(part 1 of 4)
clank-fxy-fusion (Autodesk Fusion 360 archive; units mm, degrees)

design "AS_Clank-FXY" references "AS_FXY-Z-Idler", "Bus 30 Pinner Mount", "AS_FXY-Z-Drive", "AS_FXY-XY", "AS_FXY-Z-Limit", "Bus 3010 Terminal Mount", "AS_FXY-Loadcell-Bed", "PP_EXTR_Bracket-HBLFSN5-SET", "PP_FOOD_Banana-For-Scale"
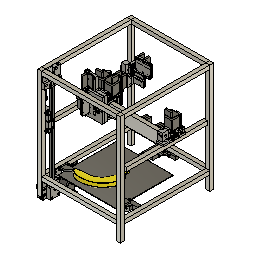
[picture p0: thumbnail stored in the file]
parameter "w_xcarr" = 107
parameter "w_ycarr" = 115.5
parameter "l_travel_x" = 256
parameter "l_travel_y" = 256
parameter "xbeam_w" = 20
parameter "xbeam_h" = 60
parameter "ybeam_w" = 20
parameter "ybeam_h" = 20
parameter "xcarr_rear_depth" = 65
parameter "yl_joint_sep" = 10
parameter "yr_joint_sep" = 11 (= "yl_joint_sep + 1 mm")
parameter "y_joints_inset" = 3
parameter "y_rear_depth" = 90
parameter "y_front_depth" = 27
parameter "l_bracket_inset" = 31
parameter "xcarr_front_depth" = 12.5
parameter "z_top_depth" = 126
parameter "z_lower_depth" = 30
parameter "l_travel_z" = 226
parameter "z_lower_offset" = 50
parameter "y_to_z_front" = 34
parameter "y_to_z_rear" = 35
sketch "Sketch1" plane through (0, 0, 0) normal (0, 0, 1) x axis (1, 0, 0)
  line L1 (369, 0) -> (0, 0)
  line L2 (369, 20) -> (369, 0)
  line L3 (0, 20) -> (369, 20)
  line L4 (0, 0) -> (0, 20)
  line L5 (-30, -51) -> (-10, -51)
  line L6 (-30, 391) -> (-30, -51)
  line L7 (-10, 391) -> (-30, 391)
  line L8 (-10, -51) -> (-10, 391)
  line L9 (400, -51) -> (380, -51)
  line L10 (400, 391) -> (400, -51)
  line L11 (380, 391) -> (400, 391)
  line L12 (380, -51) -> (380, 391)
  line L13 (-10, 393) -> (-30, 393)
  line L14 (-10, 413) -> (-10, 393)
  line L15 (-30, 413) -> (-10, 413)
  line L16 (-30, 393) -> (-30, 413)
  line L17 (-10, -53) -> (-30, -53)
  line L18 (-10, -73) -> (-10, -53)
  line L19 (-30, -73) -> (-10, -73)
  line L20 (-30, -53) -> (-30, -73)
  line L21 (380, 170) -> (-10, 170)
  line L22 (185, 20) -> (185, 170)
  line L23 (400, 393) -> (400, 413)
  line L24 (380, 393) -> (400, 393)
  line L25 (380, 413) -> (380, 393)
  line L26 (400, 413) -> (380, 413)
  line L27 (400, -53) -> (400, -73)
  line L28 (380, -53) -> (400, -53)
  line L29 (400, -73) -> (380, -73)
  line L30 (380, -73) -> (380, -53)
  line L31 (380, 393) -> (-10, 393)
  line L32 (-10, 413) -> (380, 413)
  line L33 (-30, 393) -> (-30, 391)
  line L34 (-10, 391) -> (-10, 393)
  line L35 (-30, -53) -> (-30, -51)
  line L36 (-10, -53) -> (-10, -51)
  line L37 (380, -53) -> (380, -51)
  line L38 (400, -53) -> (400, -51)
  line L39 (400, 393) -> (400, 391)
  line L40 (380, 391) -> (380, 393)
  line L41 (380, -73) -> (-10, -73)
  line L42 (380, -53) -> (-10, -53)
  point P1 (0, 0)
  point P2 (0, 0)
  point P6 (-10, -51)
  point P9 (-10, 391)
  point P8 (-30, 391)
  point P18 (-30, -53)
  point P19 (-10, -53)
  point P22 (-10, 170)
  point P23 (380, 170)
  point P24 (185, 170)
  point P25 (185, 170)
  point P26 (185, 20)
  point P27 (184.5, 20)
  point P14 (-30, 393)
  point P29 (400, 393)
  point P15 (-10, 393)
  point P30 (380, 393)
  point P16 (-10, 413)
  point P31 (380, 413)
  point P17 (-30, 413)
  point P28 (400, 413)
  point P33 (400, -53)
  point P34 (380, -53)
  point P20 (-10, -73)
  point P35 (380, -73)
  point P21 (-30, -73)
  point P32 (400, -73)
  point P36 (380, -51)
  point P7 (-30, -51)
  point P38 (400, -51)
  point P40 (400, 391)
  point P43 (380, 391)
  point P41 (400, 393)
  point P42 (380, 393)
  point P39 (400, -53)
  point P37 (380, -53)
  point P44 (0, 10)
  point P45 (-10, -53)
  point P46 (380, -53)
  point P5 (0, 20)
  point P3 (369, 0)
  point P13 (380, 391)
  horizontal L1
  vertical L2
  horizontal L3
  vertical L4
  coincident P1 P2
  horizontal L5
  vertical L6
  horizontal L7
  vertical L8
  horizontal L9
  vertical L10
  horizontal L11
  vertical L12
  equal L5 L9
  coincident P6 L9
  coincident P9 L11
  horizontal L13
  vertical L14
  horizontal L15
  vertical L16
  equal L15 L16
  coincident P8 L16
  coincident P9 L14
  horizontal L17
  vertical L18
  horizontal L19
  vertical L20
  coincident L6 P18
  coincident L8 P19
  midpoint L8 P22
  midpoint L12 P23
  midpoint L21 P24
  coincident P24 P25
  coincident L3 P26
  perpendicular L3 L22
  midpoint L3 P27
  symmetric P14 L22 P29
  symmetric P15 L22 P30
  symmetric P16 L22 P31
  symmetric P17 L22 P28
  symmetric P18 L22 P33
  symmetric P19 L22 P34
  symmetric P20 L22 P35
  symmetric P21 L22 P32
  symmetric P6 L22 P36
  symmetric P7 L22 P38
  symmetric P8 L22 P40
  symmetric P9 L22 P43
  symmetric P14 L22 P41
  symmetric P15 L22 P42
  symmetric P18 L22 P39
  symmetric P19 L22 P37
  midpoint L4 P44
  coincident P19 P45
  coincident P37 P46
  dimension "d15" distance P2 P5 = 20 (= "xbeam_w")
  dimension "d16" distance P2 P3 = 369 (= "l_travel_x + w_xcarr + 2 * y_joints_inset")
  dimension "d17" distance P1 L8 = 10 (= "yl_joint_sep")
  dimension "d18" distance P3 L12 = 11 (= "yr_joint_sep")
  dimension "d19" distance P6 P7 P13 = 20 (= "ybeam_w")
  dimension "d190" distance P7 P8 = 442 (= "l_travel_y + y_front_depth + y_rear_depth + y_to_z_front + y_to_z_rear")
  dimension "d193" distance P26 P27 = 0.5
  dimension "d198" distance P17 P21 = 486
  dimension "d199" distance P17 P28 = 430
  dimension "d272" distance L5 P44 = 61 (= "y_front_depth + y_to_z_front")
  dimension "d274" distance P8 P14 = 2
  dimension "d275" distance P18 P21 = 20
  dimension "d288" distance P7 L17 = 2
  dimension "d62" OffsetX = 0
  dimension "d63" OffsetY = 0
  dimension "d64" OffsetZ = 0
  dimension "d65" AngleZ = 0
  dimension "d74" OffsetX = 0
  dimension "d75" OffsetY = 0
  dimension "d76" OffsetZ = 0
  dimension "d77" AngleZ = 0
  dimension "d147" OffsetX = 0
  dimension "d148" OffsetY = 0
  dimension "d149" OffsetZ = 0
  dimension "d150" AngleZ = 0
  dimension "d155" OffsetX = 0
  dimension "d156" OffsetY = 0
  dimension "d157" OffsetZ = 0
  dimension "d158" AngleZ = 0
extrude "Extrude2" new body sketch "Sketch1" profile of L6 L8 L10 L12 L13 L17 L24 L28 L33 L34 L35 L36 L37 L38 L39 L40 along normal blind 20 (= "ybeam_h")
extrude "Extrude3" new body sketch "Sketch1" profile of L14 L18 L25 L30 L31 L32 L41 L42 along normal blind 20 (= "ybeam_h")
extrude "Extrude4" new body sketch "Sketch1" profile of L13 L14 L15 L16 L17 L18 L19 L20 L23 L24 L25 L26 L27 L28 L29 L30 along normal blind 496 (= "l_travel_z + z_lower_depth + z_top_depth + 114 mm") and against normal blind 75
extrude "Extrude5" sketch "Sketch1" profile of L6 L8 L10 L12 L13 L17 L24 L28 L33 L34 L35 L36 L37 L38 L39 L40 blind -20
extrude "Extrude6" sketch "Sketch1" profile of L14 L18 L25 L30 L31 L32 L41 L42 to an object
component_insert "Component Insert37"
joint "Assemble37" alignAngle -90 alignOffsetX 0 alignOffsetY 0 alignOffsetZ 0
component_insert "Component Insert38"
joint "Assemble38" alignAngle 0 alignOffsetX 0 alignOffsetY 0 alignOffsetZ 0
component_insert "Component Insert39"
joint "Assemble39" alignAngle 0 alignOffsetX 0 alignOffsetY 0 alignOffsetZ 0
component_insert "Component Insert40"
joint "Assemble40" alignAngle 90 alignOffsetX 0 alignOffsetY 0 alignOffsetZ 0
component_insert "Component Insert41"
joint "Assemble41" alignAngle 270 alignOffsetX 0 alignOffsetY 0 alignOffsetZ 0
component_insert "Component Insert16"
joint "Assemble31" alignAngle 0 alignOffsetX 0 alignOffsetY 0 alignOffsetZ 2 DistanceMinimum -351 (= "-l_travel_z - 95 mm - z_lower_depth") DistanceMaximum -125 (= "-95 mm - z_lower_depth")
component_insert "Component Insert35"
joint "Assemble35" alignAngle 90 alignOffsetX 0 alignOffsetY -0.1 alignOffsetZ 30.2
component_insert "Component Insert36"
joint "Assemble36" alignAngle 0 alignOffsetX 0 alignOffsetY -111.5 alignOffsetZ 0
position "Position1"
component_insert "Component Insert44"
joint "Assemble42" alignAngle -180 alignOffsetX 0 alignOffsetY 40.1 alignOffsetZ 0
component_insert "Component Insert22"
joint "Assemble20" alignAngle 0 alignOffsetX -75 alignOffsetY 0 alignOffsetZ 0
component_insert "Component Insert45"
joint "Assemble43" alignAngle -180 alignOffsetX 15 alignOffsetY 0 alignOffsetZ 0
component_insert "Component Insert46"
joint "Assemble44" alignAngle 180 alignOffsetX -20 alignOffsetY 0 alignOffsetZ 0
component_insert "Component Insert48"
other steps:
joint_origin "JointOrigin29"
joint_origin "JointOrigin39"
joint_origin "JointOrigin50"
joint_origin "JointOrigin51"
joint_origin "JointOrigin52"
joint_origin "JointOrigin53"
joint_origin "JointOrigin54"
joint_origin "JointOrigin55"
joint_origin "JointOrigin62"
joint_origin "JointOrigin63"
joint_origin "JointOrigin64"

design "HW_M3x14-SHCS"
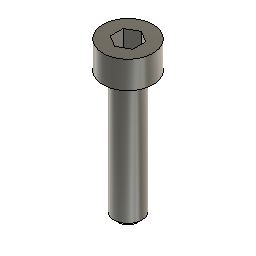
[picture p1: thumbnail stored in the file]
sketch "Sketch1" plane through (0, 0, 0) normal (0, 1, 0) x axis (1, 0, 0)
  line L1 (0, 14) -> (0, -3)
  line L2 (1.05, 14) -> (0, 14)
  line L3 (1.55, 13.5) -> (1.05, 14)
  line L4 (1.55, 0) -> (1.55, 13.5)
  line L5 (2.75, 0) -> (1.55, 0)
  line L6 (2.75, -3) -> (2.75, 0)
  line L7 (0, -3) -> (2.75, -3)
  point P1 (0, 0)
  point P4 (1.05, 14)
  point P5 (1.55, 13.5)
  point P3 (0, 14)
  point P7 (2.75, 0)
  point P8 (2.75, -3)
  point P2 (0, -3)
  vertical L1
  perpendicular L1 L2
  perpendicular L2 L4
  perpendicular L4 L5
  perpendicular L5 L6
  horizontal L7
  coincident P1 L1
  coincident P1 L5
  dimension "d1" distance P1 L2 = 14
  dimension "d2" angle L2 L3 = 45
  dimension "d3" distance P4 P5 = 0.5
  dimension "d4" distance P3 L4 = 1.55 (= "( 3.1 / 2 ) * 1 mm")
  dimension "d5" distance P7 P8 = 3
  dimension "d6" distance P2 P8 = 2.75 (= "( 5.5 / 2 ) * 1 mm")
revolve "Revolve1" sketch "Sketch1" AlongAngle 360
sketch "Sketch2" plane through (0, 0, 3) normal (0, 0, 1) x axis (-1, 0, 0)
  line L1 (0, -1.4434) -> (-1.25, -0.7217)
  line L2 (1.25, -0.7217) -> (0, -1.4434)
  line L3 (1.25, 0.7217) -> (1.25, -0.7217)
  line L4 (0, 1.4434) -> (1.25, 0.7217)
  line L5 (-1.25, 0.7217) -> (0, 1.4434)
  line L6 (-1.25, -0.7217) -> (-1.25, 0.7217)
  circle C1 centre (0, 0) radius 2.75
  point P1 (0, 0)
  point P9 (0, 0)
  point P5 (1.25, -0.7217)
  coincident P1 P9
  vertical L6
  dimension "d8" distance P5 L6 = 2.5
extrude "Extrude1" cut sketch "Sketch2" profile of L1 L2 L3 L4 L5 L6 against normal blind 2

design "PP_BRNG_624-4x13x5"
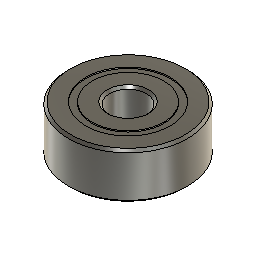
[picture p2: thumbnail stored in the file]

design "AS_FXY-Z-Limit" references "PP_SWTC_Omron-SS_5_F", "HW_M5x10-FHCS", "HW_M2x12-SHCS"
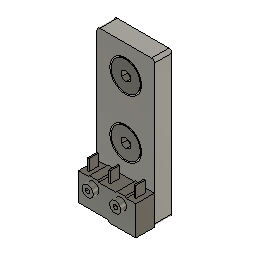
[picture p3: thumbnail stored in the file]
parameter "t_sheet_MAIN" = 7.9375
parameter "extrusion_w" = 20
parameter "extrusion_h" = 60
parameter "r_cutoutTool" = 2.05 (= "4.1 mm / 2")
parameter "od_bearings" = 13
parameter "id_bearings" = 4
parameter "t_bearings" = 5
parameter "preload" = 0.15
parameter "hw_m3_thru" = 3.5
parameter "hw_m3_thread" = 2.5
parameter "hw_m3_head" = 5.5
parameter "hw_m3_headheight" = 3
parameter "hw_m3_flathead" = 6
parameter "hw_m3_buttonhead" = 5.7
parameter "hw_m3_washer" = 7
parameter "hw_m3hex_d" = 5.5
parameter "hw_m3hex_t" = 4
parameter "hw_m3i_d" = 5.4
parameter "hw_m3i_l" = 3.8
parameter "hw_m3ichamfer" = 0.95 (= "( hw_m3i_d - hw_m3_thru ) / 2")
parameter "hw_m4_thru" = 4.25
parameter "hw_m4_head" = 7
parameter "hw_m4_headheight" = 4
parameter "hw_m4hex_d" = 7
parameter "hw_m4hex_t" = 5.2
parameter "hw_m4i_d" = 6
parameter "hw_m4i_l" = 4.8
parameter "hw_m4ichamfer" = 0.875 (= "( hw_m4i_d - hw_m4_thru ) / 2")
parameter "hw_m5_thread" = 4.2
parameter "hw_m5_head" = 8.5
parameter "hw_m5_washer" = 10
parameter "hw_m5_thru" = 5.25
parameter "hw_m6_thru" = 6.5
parameter "hw_m6_head" = 10
parameter "hw_m6_flathead" = 12
parameter "hw_m6_buttonhead" = 10.5
parameter "hw_m6_washer" = 12
parameter "p_belt" = 2
parameter "w_belt" = 10
parameter "t_belt" = 1.4
parameter "belt_pdo_toothside" = 1.15
parameter "belt_pdo_backside" = 0.25
parameter "flex_t" = 2.54
parameter "flex_l" = 5
parameter "pd_reduction" = 79.5775 (= "( nt_reduction * 2 / PI ) * 1 mm")
parameter "pd_drive" = 12.7324 (= "( nt_drive * 2 / PI ) * 1 mm")
parameter "c_dist_manuel" = 57.8
parameter "pd_pinion" = 12.7324 (= "( nt_pinion * 2 / PI ) * 1 mm")
parameter "d72" = 4
parameter "d201" = 6.35 (= "od_bearings / 2 - preload")
parameter "d236" = 5.875
parameter "d290" = 1
sketch "Sketch23" plane through (0, 0, 0) normal (0, 1, 0) x axis (1, 0, 0)
  line L1 (19.8, 0) -> (0, 0)
  line L2 (19.8, -50) -> (19.8, 0)
  line L3 (0, -50) -> (19.8, -50)
  line L4 (0, 0) -> (0, -50)
  line L5 (9.9, 0) -> (9.9, -50)
  line L6 (19.8, -10.2) -> (0, -10.2)
  line L7 (19.8, 0) -> (19.8, -10.2)
  line L8 (0, 0) -> (19.8, 0)
  line L9 (0, -10.2) -> (0, 0)
  line L10 (14.7, -7.7) -> (5.2, -7.7)
  circle C1 centre (9.9, -40.2) radius 2.75
  circle C2 centre (9.9, -40.2) radius 5.25
  circle C3 centre (9.9, -20.2) radius 2.75
  circle C4 centre (9.9, -20.2) radius 5.25
  circle C5 centre (14.7, -7.7) radius 0.9
  circle C6 centre (5.2, -7.7) radius 0.9
  point P1 (0, 0)
  point P2 (0, 0)
  point P6 (9.9, -50)
  point P7 (9.9, 0)
  point P8 (9.9, -40.2)
  point P10 (9.9, -20.2)
  point P16 (9.9, -10.2)
  point P18 (14.7, -7.7)
  point P19 (14.7, -7.7)
  point P17 (5.2, -7.7)
  point P20 (5.2, -7.7)
  point P21 (5.2, -7.7)
  point P22 (14.7, -7.7)
  point P4 (19.8, -50)
  point P5 (0, -50)
  point P9 (9.9, -40.2)
  point P11 (9.9, -20.2)
  point P3 (19.8, 0)
  point P12 (0, -10.2)
  point P13 (19.8, -10.2)
  point P15 (0, 0)
  horizontal L1
  vertical L2
  horizontal L3
  vertical L4
  coincident P1 P2
  midpoint L3 P6
  midpoint L1 P7
  coincident L5 P8
  concentric C1 C2
  coincident L5 P10
  concentric C3 C4
  equal C1 C3
  equal C2 C4
  horizontal L6
  vertical L7
  horizontal L8
  vertical L9
  midpoint L6 P16
  coincident L5 P16
  horizontal L10
  coincident P18 P19
  coincident P17 P20
  coincident P20 P21
  coincident P19 P22
  equal C5 C6
  coincident P7 L8
  dimension "d663" distance P4 P5 = 19.8
  dimension "d664" diameter C2 = 10.5
  dimension "d665" diameter C1 = 5.5
  dimension "d667" distance P9 P11 = 20
  dimension "d668" distance P3 P4 = 50
  dimension "d669" distance P12 P13 = 19.8
  dimension "d670" distance P15 L6 = 10.2
  dimension "d671" distance P17 P18 = 9.5
  dimension "d672" distance P13 P18 = 5.1
  dimension "d673" distance L6 P18 = 2.5
  dimension "d674" diameter C5 = 1.8
  dimension "d681" distance P11 L6 = 10
  dimension "d400" diameter = 12.7324 (= "pd_drive")
  dimension "d401" diameter = 79.5775 (= "pd_reduction")
  dimension "d404" distance = 42.3
  dimension "d405" distance = 31
  dimension "d406" diameter = 12.7324 (= "pd_drive")
  dimension "d408" distance = 44.7887 (= "pd_reduction / 2 + 5 mm")
  dimension "d409" distance = 57.8 (= "c_dist_manuel")
  dimension "d415" distance = 20
  dimension "d416" distance = 50
  dimension "d417" distance = 20
  dimension "d418" distance = 17 (= "15 mm + 2 mm")
  dimension "d419" angle = 94.5
  dimension "d420" angle = 16
  dimension "d421" diameter = 3.5
  dimension "d422" diameter = 6.5
  dimension "d423" radius = 11.125 (= "( 22.25 / 2 ) * 1 mm")
  dimension "d425" distance = 1.5
  dimension "d426" radius = 1.75 (= "( 3.5 / 2 ) * 1 mm")
  dimension "d427" angle = 6.5
  dimension "d428" angle = 6.4
  dimension "d429" angle = 6.4
  dimension "d430" diameter = 42
  dimension "d431" diameter = 30.1
  dimension "d432" distance = 0.5
  dimension "d433" distance = 0.1
  dimension "d434" distance = 0.1
  dimension "d435" distance = 42.7887 (= "pd_reduction / 2 + 3 mm")
  dimension "d436" distance = 20
  dimension "d437" angle = 30
  dimension "d439" distance = 127
  dimension "d441" AlongDistance = 5
  dimension "d442" TaperAngle = 0
  dimension "d443" distance = 20
  dimension "d444" distance = 0.25 (= "belt_pdo_backside")
  dimension "d445" distance = 1.15 (= "belt_pdo_toothside")
  dimension "d446" distance = 9
  dimension "d447" distance = 18
  dimension "d449" distance = 2
  dimension "d450" distance = 15
  dimension "d451" distance = 2
  dimension "d452" ProfileOffset = 0
  dimension "d453" AlongDistance = -2
  dimension "d454" TaperAngle = 0
  dimension "d455" Distance 1 = 3
  dimension "d456" Distance 2 = 2
  dimension "d457" AlongDistance = -6.75
  dimension "d458" TaperAngle = 0
  dimension "d460" distance = 2
  dimension "d461" distance = 2 (= "d460")
  dimension "d465" diameter = 5.5
  dimension "d466" diameter = 10.5
  dimension "d467" distance = 15
  dimension "d468" Distance = 0.5
  dimension "d469" Distance = 2.5
  dimension "d470" AlongDistance = 42.366
  dimension "d471" distance = 15.05 (= "( 30.1 / 2 ) * 1 mm")
  dimension "d472" distance = 1.5
  dimension "d473" distance = 1
  dimension "d475" distance = 39.7887 (= "pd_reduction / 2")
  dimension "d476" distance = 1.25
  dimension "d477" distance = 9
  dimension "d478" distance = 0.5
  dimension "d479" angle = 60
  dimension "d480" distance = 0.5
  dimension "d481" distance = 12.0207
  dimension "d482" distance = 7
  dimension "d484" angle = 45
  dimension "d485" angle = 45
  dimension "d486" distance = 6.3662 (= "pd_drive / 2")
  dimension "d491" AlongAngle = 360
  dimension "d492" diameter = 79.5775 (= "pd_reduction")
  dimension "d493" angle = 1.44 (= "( 180 / nt_reduction ) * 1 deg")
  dimension "d495" distance = 0.254
  dimension "d496" distance = 0.75
  dimension "d497" radius = 0.55
  dimension "d498" radius = 1
  dimension "d499" distance = 0.4
  dimension "d500" radius = 0.15
  dimension "d501" ProfileOffset = 0
  dimension "d502" Side1Offset = 0
  dimension "d503" TaperAngle = 0
  dimension "d505" mirrorStitchTolerance = 0.1
  dimension "d507" TotalAngle = 360
  dimension "d508" AlongAngle = 360
  dimension "d509" diameter = 12.7324 (= "pd_drive")
  dimension "d510" distance = 0.254
  dimension "d511" distance = 0.75
  dimension "d512" angle = 9 (= "( 180 / nt_drive ) * 1 deg")
  dimension "d513" radius = 1
  dimension "d514" radius = 0.55
  dimension "d515" radius = 0.15
  dimension "d516" distance = 0.4
  dimension "d517" ProfileOffset = 0
  dimension "d518" Side1Offset = 0
  dimension "d519" TaperAngle = 0
  dimension "d521" mirrorStitchTolerance = 0.1
  dimension "d522" distance = 0.05
  dimension "d524" TotalAngle = 360
  dimension "d525" distance = 0.05
  dimension "d526" distance = 1.25
  dimension "d527" distance = 0.25
  dimension "d528" distance = 0.25
  dimension "d529" AlongAngle = 360
  dimension "d530" distance = 6.5 (= "od_bearings / 2")
  dimension "d531" distance = 2 (= "id_bearings / 2")
  dimension "d532" distance = 5 (= "t_bearings")
  dimension "d533" distance = 1
  dimension "d534" distance = 2
  dimension "d535" distance = 1
  dimension "d536" distance = 1
  dimension "d537" distance = 0.5
  dimension "d541" distance = 0.25
  dimension "d542" angle = 40
  dimension "d543" distance = 0.5
  dimension "d544" distance = 0.1
  dimension "d545" distance = 0.1
  dimension "d547" distance = 9.5
  dimension "d548" distance = 0.5
  dimension "d550" distance = 2.125 (= "( 4.25 / 2 ) * 1 mm")
  dimension "d551" angle = 30
  dimension "d552" distance = 1
  dimension "d553" distance = 0.5
  dimension "d554" distance = 0.5
  dimension "d555" AlongAngle = 360
  dimension "d556" distance = 2
  dimension "d557" ProfileOffset = 0
  dimension "d558" Side1Offset = 0
  dimension "d559" TaperAngle = 0
  dimension "d560" distance = 7 (= "hw_m4hex_d")
  dimension "d561" ProfileOffset = 35
  dimension "d562" Side1Offset = 0
  dimension "d563" TaperAngle = 0
  dimension "d564" Distance = 1.8
  dimension "d565" distance = 7 (= "hw_m4hex_d")
  dimension "d566" diameter = 4.25
  dimension "d567" distance = 5
  dimension "d568" ProfileOffset = -20
  dimension "d569" Side1Offset = 0
  dimension "d570" TaperAngle = 0
  dimension "d571" Side1Offset = 0
  dimension "d572" TaperAngle = 0
  dimension "d573" Distance = 2.1
  dimension "d575" TotalAngle = 360
  dimension "d576" Distance = 0.5
  dimension "d577" Distance = 0.5
  dimension "d579" Radius = 1
  dimension "d581" Radius = 1
  dimension "d582" Distance = 0.5
  dimension "d585" distance = 12
  dimension "d586" distance = 0.5
  dimension "d587" distance = 7
  dimension "d588" distance = 7 (= "hw_m4hex_d")
  dimension "d589" diameter = 4.25
  dimension "d590" distance = 6 (= "d585 / 2")
  dimension "d591" distance = 6
  dimension "d592" distance = 7 (= "hw_m4hex_d")
  dimension "d593" diameter = 4.25
  dimension "d594" distance = 6
  dimension "d595" ProfileOffset = 0
  dimension "d596" Side1Offset = 0
  dimension "d597" TaperAngle = 0
  dimension "d598" ProfileOffset = 0.1
  dimension "d599" AlongDistance = 45
  dimension "d600" TaperAngle = 0
  dimension "d601" diameter = 9
  dimension "d602" diameter = 64
  dimension "d603" ProfileOffset = 26
  dimension "d604" Side1Offset = 0
  dimension "d605" TaperAngle = 0
  dimension "d606" ProfileOffset = 0
  dimension "d607" AlongDistance = 7
  dimension "d608" TaperAngle = 0
  dimension "d609" Distance = 2.375 (= "( ( 9 - 4.25 ) / 2 ) * 1 mm")
  dimension "d610" diameter = 11
  dimension "d611" distance = 10
  dimension "d612" distance = 10
  dimension "d613" diameter = 5.5
  dimension "d614" Side1Offset = 0
  dimension "d615" TaperAngle = 0
  dimension "d616" ProfileOffset = 0
  dimension "d617" AlongDistance = -40
  dimension "d618" TaperAngle = 0
  dimension "d620" Radius = 5.5
  dimension "d621" Distance = 2.75 (= "( ( 11 - 5.5 ) / 2 ) * 1 mm")
  dimension "d622" angle = 45 (= "( 360 / 8 ) * 1 deg")
  dimension "d623" diameter = 17
  dimension "d624" distance = 26
  dimension "d625" Side1Offset = 0
  dimension "d626" TaperAngle = 0
  dimension "d629" Distance = 1
  dimension "d631" TotalAngle = 360
  dimension "d658" alignAngle = 190
  dimension "d659" alignOffsetX = 0
  dimension "d660" alignOffsetY = 0
  dimension "d661" alignOffsetZ = 0
  dimension "d662" distance = 7
extrude "Extrude62" new body sketch "Sketch23" profile of L1 L2 L3 L4 C1 C2 C3 C4 C5 C6 along normal blind 6 bodies "Z Limit Mount"
chamfer "Chamfer33" distance 2.7
chamfer "Chamfer35" distance 0.4
fillet "Fillet13" radius 1
component_insert "Component Insert6"
joint "Assemble6" alignAngle 180 alignOffsetX 0 alignOffsetY 0 alignOffsetZ 0
component_insert "Component Insert7"
joint "Assemble7" alignAngle 180 alignOffsetX 0 alignOffsetY 0 alignOffsetZ 0
component_insert "Component Insert8"
joint "Assemble8" alignAngle 180 alignOffsetX 0 alignOffsetY 0 alignOffsetZ 0
component_insert "Component Insert11"
component_insert "Component Insert12"
joint "Assemble9" alignAngle 0 alignOffsetX 0 alignOffsetY 0 alignOffsetZ 0
joint "Assemble10" alignAngle 0 alignOffsetX 0 alignOffsetY 0 alignOffsetZ 0
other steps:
joint_origin "JointOrigin6"
joint_origin "JointOrigin7"
joint_origin "JointOrigin8"
named bodies: "Z Limit Mount"

design "M6 Cap Nut 94000A038"
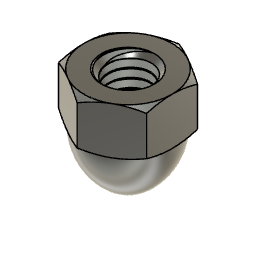
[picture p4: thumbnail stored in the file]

design "HW_M3x14-FHCS"
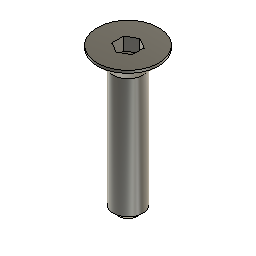
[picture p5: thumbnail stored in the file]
sketch "Sketch1" plane through (0, 0, 0) normal (0, 1, 0) x axis (1, 0, 0)
  line L1 (0, 14) -> (0, 0)
  line L2 (0.95, 14) -> (0, 14)
  line L3 (1.45, 13.5) -> (0.95, 14)
  line L4 (1.45, 1.8) -> (1.45, 13.5)
  line L5 (3, 0.25) -> (1.45, 1.8)
  line L6 (3, 0) -> (3, 0.25)
  line L7 (0, 0) -> (3, 0)
  point P1 (0, 0)
  point P2 (0, 0)
  point P9 (0, 0)
  point P3 (0, 14)
  point P4 (0.95, 14)
  point P8 (3, 0)
  point P7 (3, 0.25)
  coincident P1 P2
  vertical L1
  perpendicular L1 L2
  perpendicular L2 L4
  parallel L3 L5
  parallel L4 L6
  perpendicular L6 L7
  coincident P1 P9
  dimension "d1" distance P3 L4 = 1.45 (= "( 2.9 / 2 ) * 1 mm")
  dimension "d3" angle L2 L3 = 45
  dimension "d5" distance P4 L4 = 0.5
  dimension "d6" distance P2 P3 = 14
  dimension "d7" distance P8 P9 = 3 (= "( 6 / 2 ) * 1 mm")
  dimension "d9" distance P7 P8 = 0.25
revolve "Revolve1" sketch "Sketch1" AlongAngle 360
sketch "Sketch2" plane through (0, 0, 0) normal (0, 0, 1) x axis (-1, 0, 0)
  line L1 (0, -1.1547) -> (-1, -0.5774)
  line L2 (1, -0.5774) -> (0, -1.1547)
  line L3 (1, 0.5774) -> (1, -0.5774)
  line L4 (0, 1.1547) -> (1, 0.5774)
  line L5 (-1, 0.5774) -> (0, 1.1547)
  line L6 (-1, -0.5774) -> (-1, 0.5774)
  circle C1 centre (0, 0) radius 3
  point P1 (0, 0)
  point P9 (0, 0)
  coincident P1 P9
  vertical L6
  dimension "d12" distance L3 L6 = 2
extrude "Extrude1" cut sketch "Sketch2" profile of L1 L2 L3 L4 L5 L6 against normal blind 1.26

design "FP_HP-Pushrod"
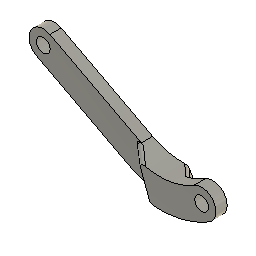
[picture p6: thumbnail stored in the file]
sketch "Sketch1" plane through (0, 0, 0) normal (0, 1, 0) x axis (1, 0, 0)
  line L1 (57.4992, 15.3) -> (0, 0)
  line L2 (43.3571, -7.7) -> (57.4992, 15.3)
  line L3 (43.3571, 19.3) -> (43.3571, -7.7)
  line L4 (30.7869, 16.1954) -> (0, 0)
  line L5 (-2.2347, 4.2481) -> (2.2347, -4.2481)
  line L6 (33.0216, 11.9473) -> (2.2347, -4.2481)
  line L7 (-2.2347, 4.2481) -> (28.5522, 20.4435)
  line L8 (33.0216, 11.9473) -> (28.5522, 20.4435)
  line L9 (35.4522, 23.1018) -> (30.8558, 10.808)
  line L10 (54.6732, 22.0184) -> (49.3571, 13.6738)
  circle C1 centre (0, 0) radius 1.625
  circle C2 centre (57.4992, 15.3) radius 1.625
  arc A1 centre (43.3571, -7.7) radius 27 clockwise from (43.3571, 19.3) to (57.4992, 15.3)
  arc A2 centre (43.3571, -7.7) radius 27 clockwise from (30.7869, 16.1954) to (43.3571, 19.3)
  arc A3 centre (43.3571, -7.7) radius 22.2 clockwise from (33.0216, 11.9473) to (54.9851, 11.2111)
  arc A4 centre (57.4992, 15.3) radius 4.8 clockwise from (60.0134, 19.3889) to (54.9851, 11.2111)
  arc A5 centre (43.3571, -7.7) radius 31.8 clockwise from (28.5522, 20.4435) to (60.0134, 19.3889)
  arc A6 centre (43.3571, -7.7) radius 27 clockwise from (30.7869, 16.1954) to (57.4992, 15.3)
  circle C3 centre (57.4992, 15.3) radius 2.3
  arc A7 centre (0, 0) radius 4.8 clockwise from (2.2347, -4.2481) to (-2.2347, 4.2481)
  circle C4 centre (0, 0) radius 2.3
  point P1 (0, 0)
  point P2 (0, 0)
  point P3 (57.4992, 15.3)
  point P5 (57.4992, 15.3)
  point P4 (0, 0)
  point P7 (57.4992, 15.3)
  point P9 (57.4992, 15.3)
  point P6 (43.3571, -7.7)
  point P10 (43.3571, -7.7)
  point P11 (43.3571, -7.7)
  point P19 (43.3571, -7.7)
  point P12 (30.7869, 16.1954)
  point P17 (30.7869, 16.1954)
  point P21 (0, 0)
  point P28 (54.6732, 22.0184)
  point P27 (49.3571, 13.6738)
  point P26 (35.4522, 23.1018)
  point P25 (30.8558, 10.808)
  point P8 (43.3571, 19.3)
  point P20 (57.4992, 15.3)
  point P24 (0, 0)
  point P16 (28.5522, 20.4435)
  coincident P1 P2
  equal C1 C2
  coincident P3 P5
  coincident P1 P4
  coincident P3 P7
  coincident P5 P9
  coincident P6 P10
  vertical L3
  coincident P6 P11
  tangent A2 L4
  tangent A3 A4
  tangent A4 A5
  coincident P6 P19
  coincident P12 P17
  concentric C2 C3
  coincident P1 P21
  coincident P2 L5
  perpendicular L4 L5
  equal A4 A7
  coincident P17 L8
  perpendicular L4 L8
  concentric C1 C4
  equal C3 C4
  coincident A5 P28
  coincident A3 P27
  coincident A5 P26
  coincident L6 P25
  dimension "d1" diameter C1 = 3.25
  dimension "d2" distance P4 P5 = 59.5 (= "56.5 mm + 3 mm")
  dimension "d6" distance P8 P10 = 27
  dimension "d7" = 31.6
  dimension "d8" diameter C3 = 4.6
  dimension "d9" distance A4 C3 = 2.5
  dimension "d10" distance P20 P24 = 15.3
  dimension "d19" distance P11 P20 = 23
  dimension "d29" angle L3 L10 = 32.5
  dimension "d30" distance L3 P27 = 6
  dimension "d38" distance P16 P26 = 6.9
  dimension "d40" angle L9 L10 = 12
extrude "Extrude4" new body sketch "Sketch1" profile of A3 A4 A5 C3 L9 L10 along normal blind 3.8 bodies "HP Pushrod"
extrude "Extrude5" new body sketch "Sketch1" profile of A3 A5 A7 L6 L7 C4 L9 L10 blind 3.8 from offset 4.2 (= "6.9 mm - 1.2 mm - 1.5 mm")
extrude "Extrude6" add sketch "Sketch1" profile of A3 A5 L6 L7 L9 L10 to an object
chamfer "Chamfer3" distance 4.2
chamfer "Chamfer4" distance 4.2
fillet "Fillet1" radius 1
named bodies: "HP Pushrod"

design "HW_M3x25-FHCS"
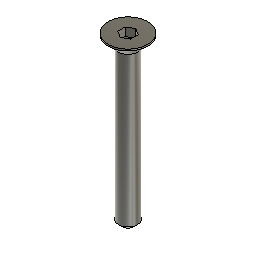
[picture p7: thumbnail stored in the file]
sketch "Sketch1" plane through (0, 0, 0) normal (0, 1, 0) x axis (1, 0, 0)
  line L1 (0, 25) -> (0, 0)
  line L2 (0.95, 25) -> (0, 25)
  line L3 (1.45, 24.5) -> (0.95, 25)
  line L4 (1.45, 1.8) -> (1.45, 24.5)
  line L5 (3, 0.25) -> (1.45, 1.8)
  line L6 (3, 0) -> (3, 0.25)
  line L7 (0, 0) -> (3, 0)
  point P1 (0, 0)
  point P2 (0, 0)
  point P9 (0, 0)
  point P3 (0, 25)
  point P4 (0.95, 25)
  point P8 (3, 0)
  point P7 (3, 0.25)
  coincident P1 P2
  vertical L1
  perpendicular L1 L2
  perpendicular L2 L4
  parallel L3 L5
  parallel L4 L6
  perpendicular L6 L7
  coincident P1 P9
  dimension "d1" distance P3 L4 = 1.45 (= "( 2.9 / 2 ) * 1 mm")
  dimension "d3" angle L2 L3 = 45
  dimension "d5" distance P4 L4 = 0.5
  dimension "d6" distance P2 P3 = 25
  dimension "d7" distance P8 P9 = 3 (= "( 6 / 2 ) * 1 mm")
  dimension "d9" distance P7 P8 = 0.25
revolve "Revolve1" sketch "Sketch1" AlongAngle 360
sketch "Sketch2" plane through (0, 0, 0) normal (0, 0, 1) x axis (-1, 0, 0)
  line L1 (0, -1.1547) -> (-1, -0.5774)
  line L2 (1, -0.5774) -> (0, -1.1547)
  line L3 (1, 0.5774) -> (1, -0.5774)
  line L4 (0, 1.1547) -> (1, 0.5774)
  line L5 (-1, 0.5774) -> (0, 1.1547)
  line L6 (-1, -0.5774) -> (-1, 0.5774)
  circle C1 centre (0, 0) radius 3
  point P1 (0, 0)
  point P9 (0, 0)
  coincident P1 P9
  vertical L6
  dimension "d12" distance L3 L6 = 2
extrude "Extrude1" cut sketch "Sketch2" profile of L1 L2 L3 L4 L5 L6 against normal blind 1.26

design "CT_Hotplate-Blade-Head" references "TE-10p-2p5-socket_1674231"
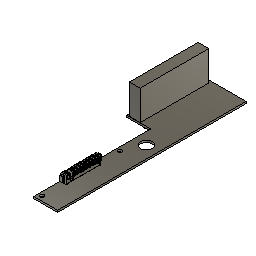
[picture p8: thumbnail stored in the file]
sketch "Sketch1" plane through (0, 0, 0) normal (0, 0, 1) x axis (1, 0, 0)
  line L1 (20, 0) -> (0, 0)
  line L2 (20, 73) -> (20, 0)
  line L3 (0, 73) -> (20, 73)
  line L4 (0, 0) -> (0, 73)
  line L5 (3, 4) -> (3, 69)
  line L6 (0, 36.5) -> (3, 36.5)
  line L7 (0, 69) -> (3, 69)
  line L8 (0, 98) -> (0, 73)
  line L9 (-20, 98) -> (0, 98)
  line L10 (-20, 158) -> (-20, 98)
  line L11 (20, 158) -> (-20, 158)
  line L12 (20, 73) -> (20, 158)
  line L13 (-9, 155.75) -> (-18, 155.75)
  line L14 (-9, 98.25) -> (-9, 155.75)
  line L15 (-18, 98.25) -> (-9, 98.25)
  line L16 (-18, 155.75) -> (-18, 98.25)
  line L17 (-11, 146) -> (-16, 146)
  line L18 (-11, 108) -> (-11, 146)
  line L19 (-16, 108) -> (-11, 108)
  line L20 (-16, 146) -> (-16, 108)
  line L21 (-9, 98.25) -> (-18, 155.75)
  line L22 (-11, 146) -> (-16, 108)
  line L23 (-1, 155) -> (-1, 158)
  line L24 (5, 155) -> (-1, 155)
  line L25 (5, 158) -> (5, 155)
  line L26 (11, 155) -> (11, 158)
  line L27 (17, 155) -> (11, 155)
  line L28 (17, 158) -> (17, 155)
  line L29 (-8.5, 102) -> (-8.5, 152)
  circle C1 centre (3, 4) radius 1.625
  circle C2 centre (3, 69) radius 1.625
  circle C3 centre (3, 69) radius 3
  circle C4 centre (10, 84.5) radius 5
  circle C5 centre (-8.5, 102) radius 1.5
  circle C6 centre (-7, 132) radius 1.5
  circle C7 centre (-8.5, 152) radius 1.5
  point P1 (0, 0)
  point P2 (0, 0)
  point P7 (3, 4)
  point P8 (3, 4)
  point P6 (3, 69)
  point P9 (3, 69)
  point P10 (3, 36.5)
  point P11 (0, 36.5)
  point P12 (3, 69)
  point P13 (0, 69)
  point P14 (1.375, 69)
  point P4 (20, 73)
  point P20 (20, 73)
  point P33 (5, 158)
  point P30 (-1, 158)
  point P34 (11, 158)
  point P37 (17, 158)
  point P32 (5, 155)
  point P38 (2, 155)
  point P39 (14, 155)
  point P40 (-13.5, 127)
  point P43 (-8.5, 152)
  point P44 (-8.5, 152)
  point P41 (-8.5, 102)
  point P45 (-8.5, 102)
  point P5 (0, 73)
  point P16 (0, 98)
  point P3 (20, 0)
  point P17 (-20, 98)
  point P18 (-20, 158)
  point P21 (-18, 155.75)
  point P22 (-9, 155.75)
  point P15 (3, 69)
  point P25 (10, 84.5)
  point P26 (-16, 146)
  point P27 (-11, 146)
  point P29 (-16, 108)
  point P23 (-9, 98.25)
  point P31 (-1, 155)
  point P42 (-7, 132)
  horizontal L1
  vertical L2
  horizontal L3
  vertical L4
  coincident P1 P2
  vertical L5
  coincident P7 P8
  coincident P6 P9
  equal C1 C2
  midpoint L5 P10
  midpoint L4 P11
  horizontal L6
  coincident P9 P12
  coincident L4 P13
  perpendicular L4 L7
  coincident C2 P14
  coincident L7 P14
  concentric C2 C3
  perpendicular L3 L8
  perpendicular L8 L9
  perpendicular L9 L10
  perpendicular L10 L11
  perpendicular L3 L12
  coincident P4 P20
  horizontal L13
  vertical L14
  horizontal L15
  vertical L16
  horizontal L17
  vertical L18
  horizontal L19
  vertical L20
  midpoint L21 L22
  vertical L23
  perpendicular L23 L24
  perpendicular L24 L25
  vertical L26
  perpendicular L26 L27
  perpendicular L27 L28
  coincident L11 P33
  coincident L11 P30
  coincident L11 P34
  coincident L11 P37
  coincident P32 L27
  equal L24 L27
  midpoint L24 P38
  midpoint L27 P39
  midpoint L21 P40
  coincident P43 P44
  coincident P41 P45
  vertical L29
  equal C6 C7
  equal C5 C7
  dimension "d1" distance P2 P5 = 73
  dimension "d2" diameter C2 = 3.25
  dimension "d3" distance P6 P7 = 65
  dimension "d4" distance P10 P11 = 3
  dimension "d5" distance L4 P14 = 1.375
  dimension "d6" diameter C3 = 6
  dimension "d13" distance P5 P16 = 25 (= "23.5 mm + 1.5 mm")
  dimension "d14" distance P2 P3 = 20
  dimension "d15" distance P17 P18 = 60
  dimension "d16" distance P16 P17 = 20
  dimension "d18" distance P21 P22 = 9
  dimension "d20" distance P17 L15 = 0.25
  dimension "d21" diameter C4 = 10
  dimension "d22" distance P15 P25 = 15.5
  dimension "d23" distance P15 P25 = 7
  dimension "d24" distance P26 P27 = 5
  dimension "d25" distance P26 P29 = 38
  dimension "d30" distance P22 P23 = 57.5
  dimension "d31" distance P31 P32 = 6
  dimension "d32" distance P38 P39 = 12
  dimension "d33" distance L10 P40 = 6.5
  dimension "d34" distance P38 P40 = 15.5
  dimension "d35" distance P30 P31 = 3
  dimension "d36" diameter C7 = 3
  dimension "d37" distance P17 L29 = 11.5
  dimension "d38" distance L9 P41 = 4
  dimension "d39" distance L11 P43 = 6
  dimension "d40" distance L10 P42 = 13
  dimension "d41" distance L9 P42 = 34
extrude "Extrude1" new body sketch "Sketch1" profile of L1 L2 L4 C1 C2 L8 L9 L10 L11 L12 L13 L14 L15 L16 C4 L17 L18 L19 L20 against normal blind 1.6
extrude "Extrude2" add sketch "Sketch1" profile of L13 L14 L15 L16 L17 L18 L19 L20 along normal blind 25
extrude "Extrude3" add sketch "Sketch1" profile of L17 L18 L19 L20 against normal blind 4.5
component_insert "Component Insert" sketch "Sketch1"
joint "Assemble1" sketch "Sketch1" alignAngle 90 alignOffsetX 0 alignOffsetY 0 alignOffsetZ 0.7
extrude "Extrude4" sketch "Sketch1" profile of L11 L23 L24 L25 L26 L27 L28 blind -3
extrude "Extrude5" sketch "Sketch1" profile of L14 C5 C6 C7 blind -3
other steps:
joint_origin "JointOrigin2" sketch "Sketch1"

design "PP_TRNS_Servo-Arm"
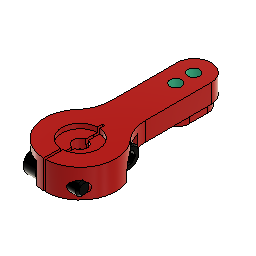
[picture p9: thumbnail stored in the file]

design "Bus 30 Pinner Mount" references "CT_UCBus-3030"
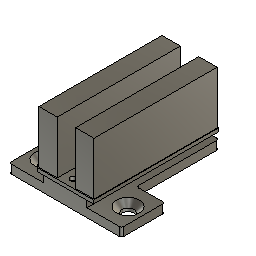
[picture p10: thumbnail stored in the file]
sketch "Sketch1" plane through (0, 0, 0) normal (0, 0, 1) x axis (1, 0, 0)
  line L1 (26, 0) -> (0, 0)
  line L2 (26, 58) -> (26, 0)
  line L3 (0, 0) -> (0, 58)
  line L4 (0, 58) -> (26, 58)
  line L5 (32, 10) -> (-6, 10)
  line L6 (-13, 20) -> (-13, 0)
  line L7 (0, 20) -> (-13, 20)
  line L8 (39, 20) -> (26, 20)
  line L9 (39, 0) -> (39, 20)
  line L10 (26, 0) -> (39, 0)
  line L11 (0, 0) -> (-13, 0)
  line L12 (3, 8) -> (3, 0)
  line L13 (23, 8) -> (3, 8)
  line L14 (23, 0) -> (23, 8)
  line L15 (3, 50) -> (3, 58)
  line L16 (23, 50) -> (3, 50)
  line L17 (23, 58) -> (23, 50)
  line L18 (13, 8) -> (13, 4)
  circle C1 centre (13, 54) radius 1.35
  circle C2 centre (13, 4) radius 1.35
  circle C3 centre (-6, 10) radius 2.75
  circle C4 centre (32, 10) radius 2.75
  circle C5 centre (-6, 10) radius 5
  point P1 (0, 0)
  point P2 (0, 0)
  point P8 (-6, 10)
  point P11 (-6, 10)
  point P9 (32, 10)
  point P12 (32, 10)
  point P15 (0, 20)
  point P16 (26, 20)
  point P3 (26, 0)
  point P19 (26, 0)
  point P20 (0, 0)
  point P21 (3, 0)
  point P24 (23, 0)
  point P25 (3, 58)
  point P28 (23, 58)
  point P7 (13, 4)
  point P29 (13, 4)
  point P30 (13, 8)
  point P22 (3, 8)
  point P23 (23, 8)
  point P4 (26, 58)
  point P5 (0, 58)
  point P6 (13, 54)
  point P10 (-6, 10)
  point P13 (-13, 0)
  point P14 (-13, 20)
  horizontal L1
  vertical L2
  horizontal L4
  vertical L3
  coincident P1 P2
  equal C1 C2
  equal C3 C4
  concentric C3 C5
  coincident P8 P11
  coincident P9 P12
  horizontal L5
  parallel L3 L6
  coincident L3 P15
  perpendicular L3 L7
  coincident L2 P16
  perpendicular L2 L8
  perpendicular L8 L9
  perpendicular L2 L10
  coincident P3 P19
  perpendicular L6 L11
  coincident P1 P20
  coincident L7 P16
  equal L7 L8
  coincident L1 P21
  perpendicular L1 L12
  perpendicular L12 L13
  coincident L1 P24
  perpendicular L1 L14
  coincident L4 P25
  perpendicular L4 L15
  perpendicular L15 L16
  coincident L4 P28
  perpendicular L4 L17
  coincident P7 P29
  midpoint L13 P30
  vertical L18
  coincident P22 L15
  coincident P23 L17
  equal L12 L15
  dimension "d1" distance P4 P5 = 26
  dimension "d2" distance P2 P5 = 58
  dimension "d3" distance P6 L4 = 4
  dimension "d6" diameter C1 = 2.7
  dimension "d7" distance L3 P6 = 13 (= "d1 / 2")
  dimension "d25" distance L1 P7 = 4
  dimension "d26" distance L3 P7 = 13 (= "d7")
  dimension "d50" diameter C3 = 5.5
  dimension "d51" diameter C5 = 10
  dimension "d52" distance P3 L5 = 10
  dimension "d53" distance P7 P10 = 19
  dimension "d54" distance P7 P9 = 19
  dimension "d55" distance P10 L6 = 7
  dimension "d56" distance P13 P14 = 20
  dimension "d57" distance P21 P22 = 8
  dimension "d58" distance P22 P23 = 20
extrude "Extrude1" new body sketch "Sketch1" profile of L1 L2 L4 L3 C1 C2 C3 C4 L6 L7 L8 L9 L10 L11 along normal blind 4
chamfer "Chamfer1" distance 2.5
extrude "Extrude4" sketch "Sketch1" profile of L1 L4 C1 C2 L12 L13 L14 L15 L16 L17 blind 3
fillet "Fillet1" radius 1
component_insert "Component Insert"
joint "Assemble1" alignAngle 0 alignOffsetX 0 alignOffsetY 0 alignOffsetZ 0
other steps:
joint_origin "JointOrigin1"

design "FP_UCBus-3010-X-Mount"
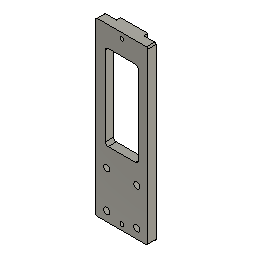
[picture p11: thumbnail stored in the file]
sketch "Sketch1" plane through (0, 0, 0) normal (0, 1, 0) x axis (1, 0, 0)
  line L1 (38, 0) -> (0, 0)
  line L2 (38, -125) -> (38, 0)
  line L3 (0, -125) -> (38, -125)
  line L4 (0, 0) -> (0, -125)
  line L5 (19, -121) -> (19, -125)
  line L6 (19, -4) -> (19, 0)
  line L7 (9, -117) -> (9, -125)
  line L8 (29, -117) -> (9, -117)
  line L9 (29, -125) -> (29, -117)
  line L10 (19, -117) -> (19, -121)
  line L11 (13, -8) -> (13, 0)
  line L12 (25, -8) -> (13, -8)
  line L13 (25, 0) -> (25, -8)
  line L14 (19, -8) -> (19, -4)
  line L15 (30, -34) -> (8, -34)
  line L16 (30, -7) -> (30, -34)
  line L17 (8, -7) -> (30, -7)
  line L18 (8, -34) -> (8, -7)
  line L19 (19, -8) -> (19, -34)
  line L20 (31, -48) -> (7, -48)
  line L21 (31, -110) -> (31, -48)
  line L22 (7, -110) -> (31, -110)
  line L23 (7, -48) -> (7, -110)
  circle C1 centre (19, -121) radius 1.35
  circle C2 centre (19, -4) radius 1.35
  circle C3 centre (8, -34) radius 2.25
  circle C4 centre (30, -34) radius 2.25
  circle C5 centre (8, -7) radius 2.25
  circle C6 centre (30, -7) radius 2.25
  point P1 (0, 0)
  point P2 (0, 0)
  point P6 (19, -125)
  point P8 (19, 0)
  point P7 (19, -121)
  point P10 (19, -121)
  point P9 (19, -4)
  point P11 (19, -4)
  point P12 (9, -125)
  point P15 (29, -125)
  point P16 (19, -121)
  point P17 (19, -117)
  point P18 (13, 0)
  point P21 (25, 0)
  point P22 (19, -4)
  point P23 (19, -8)
  point P24 (8, -34)
  point P28 (8, -34)
  point P25 (30, -34)
  point P29 (30, -34)
  point P27 (8, -7)
  point P30 (8, -7)
  point P26 (30, -7)
  point P31 (30, -7)
  point P32 (19, -34)
  point P3 (38, 0)
  point P5 (0, -125)
  point P13 (9, -117)
  point P14 (29, -117)
  point P19 (13, -8)
  point P20 (25, -8)
  horizontal L1
  vertical L2
  horizontal L3
  vertical L4
  coincident P1 P2
  midpoint L3 P6
  perpendicular L3 L5
  midpoint L1 P8
  perpendicular L1 L6
  coincident P7 P10
  coincident P9 P11
  equal C1 C2
  equal L5 L6
  coincident L3 P12
  perpendicular L3 L7
  perpendicular L7 L8
  coincident L3 P15
  perpendicular L3 L9
  coincident P10 P16
  midpoint L8 P17
  vertical L10
  coincident L1 P18
  perpendicular L1 L11
  perpendicular L11 L12
  coincident L1 P21
  perpendicular L1 L13
  coincident P11 P22
  midpoint L12 P23
  vertical L14
  horizontal L15
  vertical L16
  horizontal L17
  vertical L18
  equal C5 C6
  equal C4 C6
  equal C3 C4
  coincident P24 P28
  coincident P25 P29
  coincident P27 P30
  coincident P26 P31
  midpoint L15 P32
  vertical L19
  horizontal L20
  vertical L21
  horizontal L22
  vertical L23
  dimension "d1" distance P2 P3 = 38
  dimension "d2" distance P2 P5 = 125
  dimension "d3" diameter C1 = 2.7
  dimension "d4" distance P6 P7 = 4
  dimension "d6" distance P13 P14 = 20
  dimension "d7" distance P12 P13 = 8
  dimension "d8" distance P19 P20 = 12
  dimension "d9" distance P18 P19 = 8
  dimension "d10" distance P24 P25 = 22
  dimension "d11" distance P24 P27 = 27
  dimension "d12" diameter C3 = 4.5
  dimension "d13" distance P3 L17 = 7
  dimension "d19" distance L2 L21 = 7
  dimension "d20" distance L4 L23 = 7 (= "d19")
  dimension "d21" distance P14 L22 = 7 (= "d19")
  dimension "d22" distance P29 L20 = 14
extrude "Extrude1" new body sketch "Sketch1" profile of L1 L2 L3 L4 L7 L8 L9 L11 L12 L13 C3 C4 C5 C6 L20 L21 L22 L23 along normal blind 6
extrude "Extrude2" add sketch "Sketch1" profile of L1 L3 C1 C2 L7 L8 L9 L11 L12 L13 to an object offset 3
chamfer "Chamfer1" distance 2
fillet "Fillet1" radius 1
fillet "Fillet2" radius 2

design "10x30 M6 Dowel 97355A500"
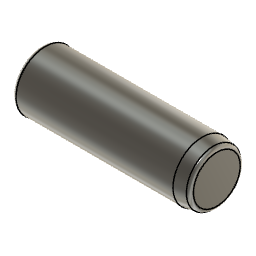
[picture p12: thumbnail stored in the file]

design "HW_M2x12-SHCS"
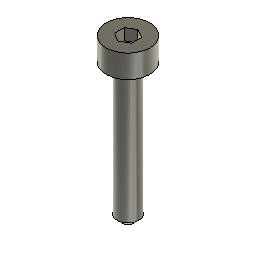
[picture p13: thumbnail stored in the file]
sketch "Sketch1" plane through (0, 0, 0) normal (0, 1, 0) x axis (1, 0, 0)
  line L1 (0, 12) -> (0, -2)
  line L2 (0.45, 12) -> (0, 12)
  line L3 (0.95, 11.5) -> (0.45, 12)
  line L4 (0.95, 0) -> (0.95, 11.5)
  line L5 (1.9, 0) -> (0.95, 0)
  line L6 (1.9, -2) -> (1.9, 0)
  line L7 (0, -2) -> (1.9, -2)
  point P1 (0, 0)
  point P4 (0.45, 12)
  point P5 (0.95, 11.5)
  point P3 (0, 12)
  point P7 (1.9, 0)
  point P8 (1.9, -2)
  point P2 (0, -2)
  vertical L1
  perpendicular L1 L2
  perpendicular L2 L4
  perpendicular L4 L5
  perpendicular L5 L6
  horizontal L7
  coincident P1 L1
  coincident P1 L5
  dimension "d1" distance P1 L2 = 12
  dimension "d2" angle L2 L3 = 45
  dimension "d3" distance P4 P5 = 0.5
  dimension "d4" distance P3 L4 = 0.95 (= "( 1.9 / 2 ) * 1 mm")
  dimension "d5" distance P7 P8 = 2
  dimension "d6" distance P2 P8 = 1.9 (= "( 3.8 / 2 ) * 1 mm")
revolve "Revolve1" sketch "Sketch1" AlongAngle 360
sketch "Sketch2" plane through (0, 0, 2) normal (0, 0, 1) x axis (-1, 0, 0)
  line L1 (0, -0.866) -> (-0.75, -0.433)
  line L2 (0.75, -0.433) -> (0, -0.866)
  line L3 (0.75, 0.433) -> (0.75, -0.433)
  line L4 (0, 0.866) -> (0.75, 0.433)
  line L5 (-0.75, 0.433) -> (0, 0.866)
  line L6 (-0.75, -0.433) -> (-0.75, 0.433)
  circle C1 centre (0, 0) radius 1.9
  point P1 (0, 0)
  point P9 (0, 0)
  point P5 (0.75, -0.433)
  coincident P1 P9
  vertical L6
  dimension "d8" distance P5 L6 = 1.5
extrude "Extrude1" cut sketch "Sketch2" profile of L1 L2 L3 L4 L5 L6 against normal blind 1

design "BHCS M6x8 92095A239"
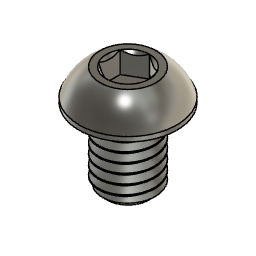
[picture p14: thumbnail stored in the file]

design "AS_FXY-YL" references "PP_ACTU_N17-Stepper", "AS_Flanged-Idler", "PP_TRNS_GT2-Pulley-20T-10mm", "HW_M3-Washer", "PP_SWTC_Omron-SS_5_F", "HW_M4-Nylock", "HW_M4-Washer", "AS_Pinched-Roller", "HW_M3x10-SHCS", "HW_M2x12-SHCS", "HW_M4x40-FHCS", "AS_Single-Roller", "HW_M4x14-BHCS", "HW_M4x30-BHCS"
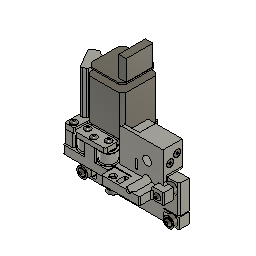
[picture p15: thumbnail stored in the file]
parameter "t_sheet_MAIN" = 9.5
parameter "extrusion_w" = 20
parameter "extrusion_h" = 20
parameter "r_cutoutTool" = 2.05 (= "4.1 mm / 2")
parameter "od_bearings" = 13
parameter "id_bearings" = 4
parameter "t_bearings" = 5
parameter "preload" = 0.15
parameter "hw_m3_thru" = 3.5
parameter "hw_m3_thread" = 2.5
parameter "hw_m3_head" = 5.5
parameter "hw_m3_headheight" = 3
parameter "hw_m3_flathead" = 6
parameter "hw_m3_buttonhead" = 5.7
parameter "hw_m3_washer" = 7
parameter "hw_m3hex_d" = 5.5
parameter "hw_m3hex_t" = 4
parameter "hw_m3i_d" = 5.4
parameter "hw_m3i_l" = 3.8
parameter "hw_m3ichamfer" = 0.95 (= "( hw_m3i_d - hw_m3_thru ) / 2")
parameter "hw_m4_thru" = 4.25
parameter "hw_m4_head" = 7
parameter "hw_m4_headheight" = 4
parameter "hw_m4hex_d" = 7
parameter "hw_m4hex_t" = 5.2
parameter "hw_m4i_d" = 6
parameter "hw_m4i_l" = 4.8
parameter "hw_m4ichamfer" = 0.875 (= "( hw_m4i_d - hw_m4_thru ) / 2")
parameter "hw_m5_thread" = 4.2
parameter "hw_m5_head" = 8.5
parameter "hw_m5_washer" = 10
parameter "hw_m5_thru" = 5.25
parameter "hw_m6_thru" = 6.5
parameter "hw_m6_head" = 10
parameter "hw_m6_flathead" = 12
parameter "hw_m6_buttonhead" = 10.5
parameter "hw_m6_washer" = 12
parameter "p_belt" = 1.4
parameter "w_belt" = 10
parameter "t_belt" = 1.4
parameter "belt_pdo_toothside" = 1.15
parameter "belt_pdo_backside" = 0.25
parameter "t_m4_washer" = 0.85
parameter "flex_t" = 2.54
parameter "flex_l" = 5
parameter "t_motor_plates" = 6 comment "5/16 Phenolic"
parameter "d650" = 1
